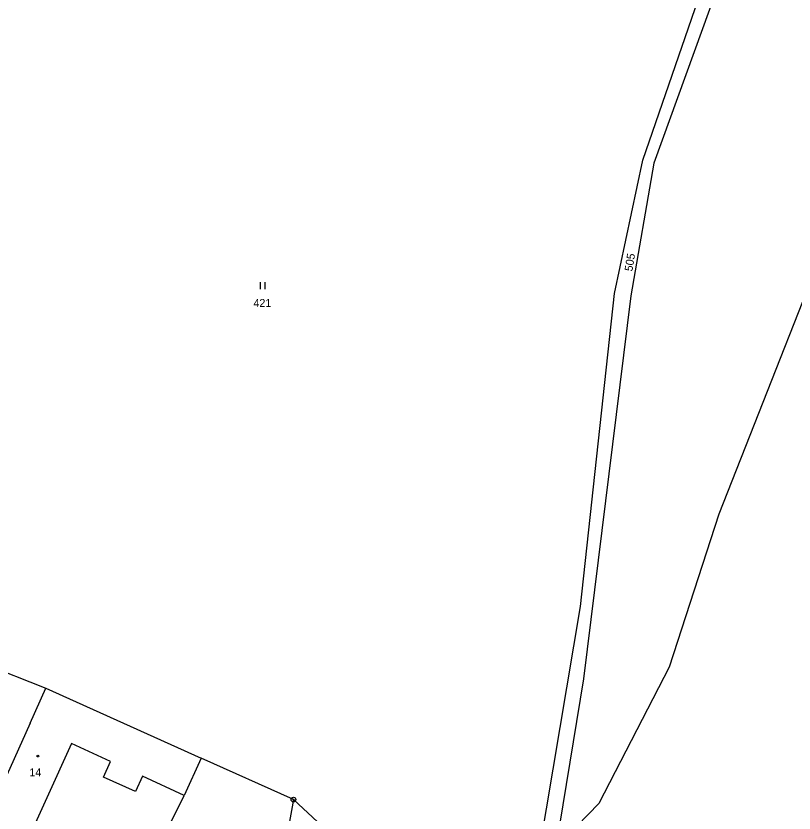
# Model space of a CAD drawing. Extents: x -547623 to -538651, y -1096714 to -1086522.
# Drawn here: x -543751.8 to -543586.5, y -1094371 to -1094201.7 of the extents above; entities that cross this region are included whole.
import ezdxf

# ---------------------------------------------------------------- set-up
doc = ezdxf.new("R2010")
doc.units = 0
for name, color, linetype in [('Vrstva 1', 7, 'Continuous'), ('Vrstva 25', 7, 'Continuous'), ('Vrstva 33', 7, 'Continuous'), ('Vrstva 52', 7, 'Continuous'), ('Vrstva 83', 7, 'Continuous'), ('Vrstva 86', 7, 'Continuous'), ('Vrstva 90', 7, 'Continuous'), ('Vrstva 92', 7, 'Continuous')]:
    doc.layers.add(name, color=color, linetype=linetype)

msp = doc.modelspace()

# ---------------------------------------------------------------- linework, layer by layer
at = {"layer": 'Vrstva 1'}
for points in [[(-543618.61, -1094232.29), (-543605.43, -1094194.07)], [(-543602.66, -1094195.34), (-543616.25, -1094232.92)], [(-543624.63, -1094260.66), (-543618.61, -1094232.29)], [(-543616.25, -1094232.92), (-543621.14, -1094261.13)], [(-543631.88, -1094327.17), (-543624.63, -1094260.66)], [(-543621.14, -1094261.13), (-543631.25, -1094342.54)], [(-543641.97, -1094387.42), (-543631.88, -1094327.17)], [(-543758.74, -1094339.27), (-543745.46, -1094344.49)], [(-543631.25, -1094342.54), (-543639.32, -1094391.75)], [(-543748.81, -1094351.91), (-543745.46, -1094344.49)], [(-543745.46, -1094344.49), (-543712.48, -1094359.37)], [(-543748.81, -1094351.91), (-543759.69, -1094376.09)], [(-543712.48, -1094359.37), (-543716.05, -1094367.29)], [(-543692.85, -1094368.16), (-543712.48, -1094359.37)], [(-543729.13, -1094393.56), (-543716.05, -1094367.29)], [(-543692.85, -1094368.16), (-543697.42, -1094393.4)], [(-543644.99, -1094412.67), (-543692.85, -1094368.16)]]:
    msp.add_lwpolyline(points, dxfattribs=at)
at = {"layer": 'Vrstva 25'}
for p, q in [((-543699.82, -1094259.73), (-543699.82, -1094258.23)), ((-543698.82, -1094259.73), (-543698.82, -1094258.23))]:
    msp.add_line(p, q, dxfattribs=at)
msp.add_circle((-543747.14, -1094358.93), 0.175, dxfattribs=at)
at = {"layer": 'Vrstva 33'}
for points in [[(-543740.03, -1094356.25), (-543750.81, -1094380.13)], [(-543731.73, -1094360.07), (-543740.03, -1094356.25)], [(-543733.23, -1094363.37), (-543731.73, -1094360.07)], [(-543726.4, -1094366.45), (-543733.23, -1094363.37)], [(-543724.94, -1094363.2), (-543726.4, -1094366.45)], [(-543716.05, -1094367.29), (-543724.94, -1094363.2)]]:
    msp.add_lwpolyline(points, dxfattribs=at)
at = {"layer": 'Vrstva 52'}
msp.add_lwpolyline([(-543573.5, -1094234), (-543602.5, -1094307.5), (-543613, -1094340), (-543628, -1094369), (-543637.14, -1094378.47), (-543641.17, -1094382.64), (-543656, -1094398), (-543659.46, -1094399.21), (-543681.88, -1094407.09), (-543689.09, -1094409.62), (-543691.68, -1094410.53), (-543707.72, -1094416.17), (-543741.12, -1094427.9), (-543750, -1094431.02), (-543752.84, -1094432.02), (-543758.72, -1094434.08), (-543760.05, -1094434.55), (-543760.72, -1094434.33), (-543760.31, -1094434.64), (-543761.19, -1094434.95), (-543777, -1094440.5)], dxfattribs=at)
at = {"layer": 'Vrstva 83'}
for radius in [0.5, 0.1]:
    msp.add_circle((-543692.85, -1094368.16), radius, dxfattribs=at)
at = {"layer": 'Vrstva 90'}
for points in [[(-543748.81, -1094351.91), (-543745.46, -1094344.49)], [(-543745.46, -1094344.49), (-543712.48, -1094359.37)], [(-543748.81, -1094351.91), (-543759.69, -1094376.09)], [(-543740.03, -1094356.25), (-543750.81, -1094380.13)], [(-543731.73, -1094360.07), (-543740.03, -1094356.25)], [(-543733.23, -1094363.37), (-543731.73, -1094360.07)], [(-543712.48, -1094359.37), (-543716.05, -1094367.29)], [(-543726.4, -1094366.45), (-543733.23, -1094363.37)], [(-543724.94, -1094363.2), (-543726.4, -1094366.45)], [(-543716.05, -1094367.29), (-543724.94, -1094363.2)]]:
    msp.add_lwpolyline(points, dxfattribs=at)

# ---------------------------------------------------------------- texts
at = {"layer": 'Vrstva 86'}
msp.add_text('505', height=1.7, rotation=80.6852, dxfattribs=at).set_placement((-543620.85, -1094256.01))
msp.add_text('421', height=1.7, dxfattribs=at).set_placement((-543701.34, -1094263.5))
at = {"layer": 'Vrstva 92'}
msp.add_text('14', height=1.7, dxfattribs=at).set_placement((-543748.95, -1094363.22))

doc.saveas('drawing.dxf')
